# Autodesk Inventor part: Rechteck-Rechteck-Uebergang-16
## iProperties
Created: 2005-05
Part Number: Rechteck-Rechteck-Uebergang-16
Material: .
Document SubType Name: Blech
Designer: rsc
Manufacturer: Standard
Standards Organization: Custom
Kanten: brechen
Oberflächen: Ra 3,2
Radien: 2
Toleranzen: ISO 2768 - m
Author: rsc
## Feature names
1. Erhebung3
2. Trennen3
3. Trennen4
4. Rundung2 [Fillet]
5. Wandstärke3
6. ExtrusionAbwicklung1
7. Ecke1
